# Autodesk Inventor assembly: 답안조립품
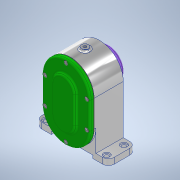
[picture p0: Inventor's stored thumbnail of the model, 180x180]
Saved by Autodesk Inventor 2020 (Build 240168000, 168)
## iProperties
Created: 2021-05
Part Number: 답안조립품
Document SubType Name: Assembly
Designer: Owner
Author: Owner
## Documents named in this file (19)
- C:\Users\Owner\Desktop\710507V1006\답안조립품.iam
- C:\Users\Owner\Desktop\710507V1006\본체.ipt
- C:\Users\Owner\Desktop\710507V1006\오일 실 12 22 7.ipt
- C:\Users\Owner\Desktop\710507V1006\커버 B.ipt
- C:\Users\Owner\Desktop\710507V1006\베어링 6001.ipt
- 베어링 6001.ipt
- C:\Users\Owner\Desktop\710507V1006\칼라.ipt
- C:\Users\Owner\Desktop\710507V1006\축 A.ipt
- C:\Users\Owner\Desktop\710507V1006\키 5 x 5 x 12.ipt
- C:\Users\Owner\Desktop\710507V1006\스퍼기어 A.ipt
- C:\Users\Owner\Desktop\710507V1006\축 B.ipt
- C:\Users\Owner\Desktop\710507V1006\키 4 x 4 x 12.ipt
- C:\Users\Owner\Desktop\710507V1006\스퍼기어 B.ipt
- C:\Users\Owner\Desktop\710507V1006\커버 A.ipt
- C:\Users\Owner\Desktop\710507V1006\볼트 M4.ipt
- C:\Users\Owner\Desktop\710507V1006\베어링 6002.ipt
- 베어링 6002.ipt
- C:\Users\Owner\Desktop\710507V1006\개스킷 A.ipt
- C:\Users\Owner\Desktop\710507V1006\개스킷 B.ipt
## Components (2 placed, 2 different names)
1. 개스킷 A:1
2. 개스킷 B:1
